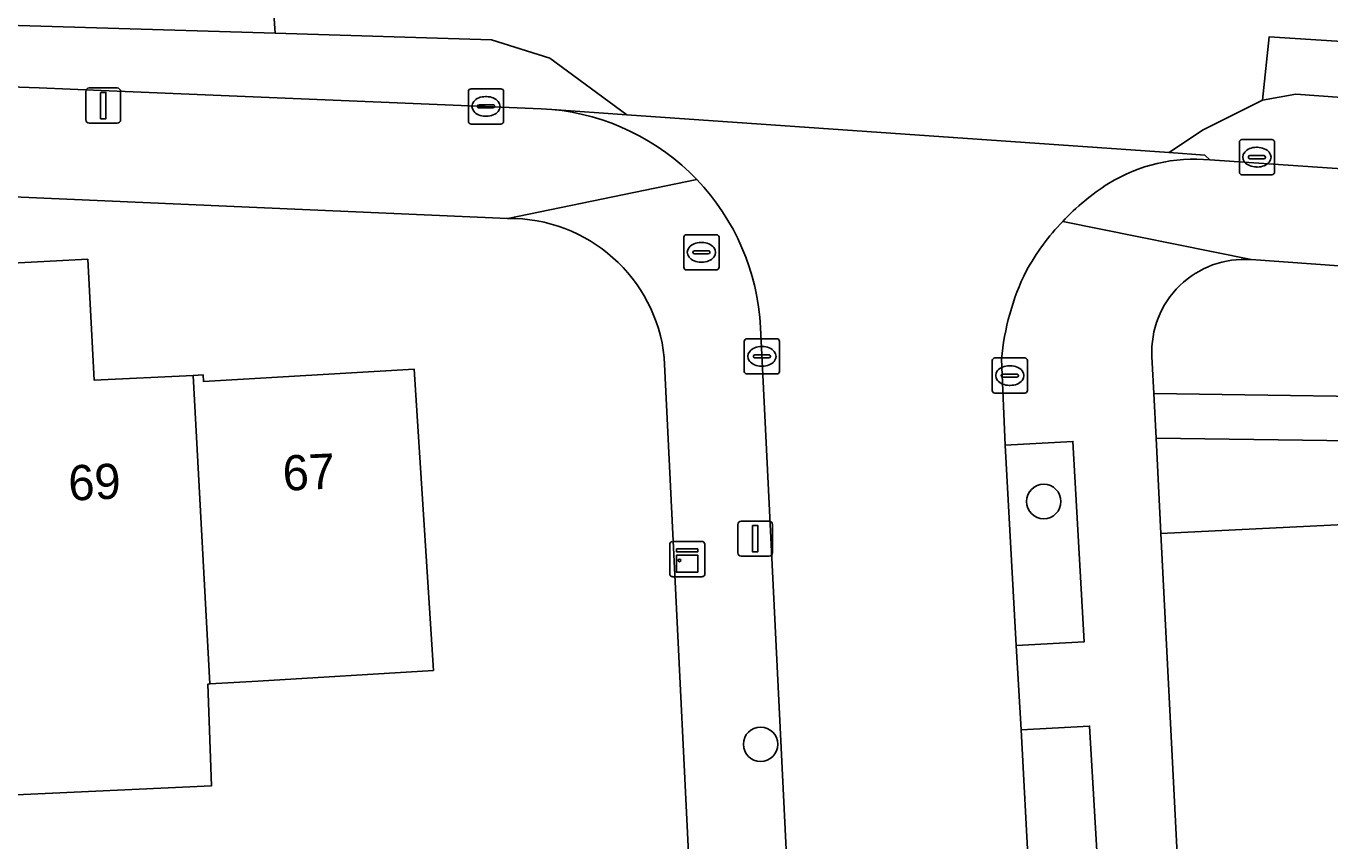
# Model space of a CAD drawing. Extents: x 161084 to 161928, y 385354 to 386522.
# Drawn here: x 161294.37 to 161331.43, y 386132.82 to 386155.98 of the extents above; entities that cross this region are included whole.
import ezdxf

# ---------------------------------------------------------------- set-up
doc = ezdxf.new("R2010")
doc.units = 0
for name, color, linetype in [('IMGEO_Boom', 7, 'Continuous'), ('IMGEO_Brandkraan', 7, 'Continuous'), ('IMGEO_Erf', 7, 'Continuous'), ('IMGEO_Groenvoorziening', 7, 'Continuous'), ('IMGEO_Hek', 7, 'Continuous'), ('IMGEO_Kast', 7, 'Continuous'), ('IMGEO_Kolk', 7, 'Continuous'), ('IMGEO_Lichtmast', 7, 'Continuous'), ('IMGEO_Pand', 7, 'Continuous'), ('IMGEO_Pand_nummerreeks', 7, 'Continuous'), ('IMGEO_Parkeervlak_gesloten', 7, 'Continuous'), ('IMGEO_Rijbaan_lokaal_gesloten', 7, 'Continuous'), ('IMGEO_Rijbaan_lokaal_open', 7, 'Continuous'), ('IMGEO_Voetpad_open', 7, 'Continuous')]:
    doc.layers.add(name, color=color, linetype=linetype)

msp = doc.modelspace()

# ---------------------------------------------------------------- linework, layer by layer
at = {"layer": 'IMGEO_Boom'}
for centre in [(161323.299, 386142.465), (161315.249, 386135.563)]:
    msp.add_circle(centre, 0.489, dxfattribs=at)
at = {"layer": 'IMGEO_Brandkraan'}
for p, q in [((161313.067, 386149.123), (161313.067, 386149.975)), ((161313.142, 386150.049), (161313.994, 386150.049)), ((161313.555, 386149.829), (161313.58, 386149.829)), ((161314.068, 386149.975), (161314.068, 386149.123)), ((161313.326, 386149.543), (161313.326, 386149.555)), ((161313.764, 386149.506), (161313.366, 386149.506)), ((161313.369, 386149.592), (161313.767, 386149.592)), ((161313.81, 386149.555), (161313.81, 386149.543)), ((161313.994, 386149.049), (161313.142, 386149.049)), ((161313.578, 386149.269), (161313.553, 386149.269))]:
    msp.add_line(p, q, dxfattribs=at)
for points in [[(161313.067, 386149.123), (161313.067, 386149.975)], [(161313.142, 386150.049), (161313.994, 386150.049)], [(161314.068, 386149.975), (161314.068, 386149.123)], [(161313.994, 386149.049), (161313.142, 386149.049)]]:
    msp.add_lwpolyline(points, dxfattribs=at)
for centre, radius, start, end in [((161313.144, 386149.973), 0.0765, 91.552, 178.448), ((161313.144, 386149.973), 0.0765, 91.552, 178.448), ((161313.992, 386149.973), 0.0765, 1.552, 88.448), ((161313.992, 386149.973), 0.0765, 1.552, 88.448), ((161313.366, 386149.552), 0.0403, 85.8775, 175.7526), ((161313.363, 386149.542), 0.0366, 178.938, 274.7102), ((161313.767, 386149.549), 0.043, 264.8664, 352.4533), ((161313.771, 386149.554), 0.0386, 1.7309, 96.639), ((161313.144, 386149.125), 0.0765, 181.552, 268.448), ((161313.144, 386149.125), 0.0765, 181.552, 268.448), ((161313.992, 386149.125), 0.0765, 271.552, 358.448), ((161313.992, 386149.125), 0.0765, 271.552, 358.448)]:
    msp.add_arc(centre, radius, start, end, dxfattribs=at)
for centre, major_axis, ratio, start_param, end_param in [((161313.554, 386149.549), (-0.387, 0.002), 0.722429, 4.712389, 7.853982), ((161313.579, 386149.549), (-0.39, 0.002), 0.717154, 1.570796, 4.712389)]:
    msp.add_ellipse(centre, major_axis=major_axis, ratio=ratio, start_param=start_param, end_param=end_param, dxfattribs=at)
at = {"layer": 'IMGEO_Erf'}
for points in [[(161308.06, 386150.51), (161293.144, 386151.165)], [(161292.892, 386149.179), (161296.121, 386149.354), (161296.307, 386145.913), (161299.12, 386146.051), (161299.406, 386146.065), (161299.417, 386145.876), (161305.406, 386146.224), (161305.951, 386137.661), (161300.961, 386137.353), (161299.596, 386137.278), (161299.538, 386137.273), (161299.638, 386134.377), (161293.683, 386134.108)], [(161293.068, 386124.722), (161295.221, 386124.913), (161295.092, 386127.372), (161300.05, 386127.633), (161300.18, 386125.161), (161301.546, 386125.23), (161301.425, 386127.712), (161306.376, 386127.954), (161306.19, 386131.777), (161309.467, 386131.936), (161309.774, 386125.631), (161313.524, 386125.898), (161312.512, 386146.555)], [(161360.195, 386143.207), (161326.629, 386141.553), (161328.624, 386102.307), (161328.778, 386099.301), (161331.2, 386051.66), (161334.752, 386051.846)]]:
    msp.add_lwpolyline(points, dxfattribs=at)
msp.add_arc((161308.121, 386146.096), 4.415, 5.9705, 90.796, dxfattribs=at)
at = {"layer": 'IMGEO_Groenvoorziening'}
msp.add_lwpolyline([(161326.373, 386146.591), (161326.427, 386145.537), (161335.501, 386145.4), (161335.504, 386144.14), (161326.491, 386144.261), (161326.629, 386141.553), (161360.195, 386143.207), (161360.035, 386147.116), (161329.193, 386149.342)], dxfattribs=at)
for points in [[(161324.127, 386144.171), (161322.2, 386144.068), (161322.511, 386138.373), (161324.449, 386138.477)], [(161324.604, 386136.078), (161322.66, 386135.974), (161323.107, 386127.582), (161325.094, 386127.695)]]:
    msp.add_lwpolyline(points, close=True, dxfattribs=at)
msp.add_arc((161329.002, 386146.717), 2.632, 85.8341, 182.7467, dxfattribs=at)
at = {"layer": 'IMGEO_Hek'}
msp.add_lwpolyline([(161326.629, 386141.553), (161360.195, 386143.207)], dxfattribs=at)
at = {"layer": 'IMGEO_Kast'}
for p, q in [((161312.666, 386140.403), (161312.666, 386141.244)), ((161312.666, 386141.244), (161312.666, 386140.403)), ((161312.741, 386141.328), (161313.582, 386141.328)), ((161313.582, 386141.328), (161312.741, 386141.328)), ((161313.666, 386141.253), (161313.666, 386140.412)), ((161313.666, 386140.412), (161313.666, 386141.253)), ((161313.591, 386140.328), (161312.75, 386140.328)), ((161312.75, 386140.328), (161313.591, 386140.328))]:
    msp.add_line(p, q, dxfattribs=at)
for points in [[(161312.861, 386141.118), (161313.461, 386141.118), (161313.461, 386141.033), (161312.861, 386141.033), (161312.861, 386141.118)], [(161312.861, 386140.943), (161313.461, 386140.943), (161313.461, 386140.454), (161312.861, 386140.454), (161312.861, 386140.943)]]:
    msp.add_lwpolyline(points, dxfattribs=at)
msp.add_circle((161312.945, 386140.792), 0.0377, dxfattribs=at)
for centre, start, end in [((161312.744, 386141.25), 92.4484, 184.2845), ((161312.744, 386141.25), 92.4484, 184.2845), ((161313.588, 386141.25), 2.4484, 94.2845), ((161313.588, 386141.25), 2.4484, 94.2845), ((161312.744, 386140.406), 182.4484, 274.2845), ((161312.744, 386140.406), 182.4484, 274.2845), ((161313.588, 386140.406), 272.4484, 4.2845), ((161313.588, 386140.406), 272.4484, 4.2845)]:
    msp.add_arc(centre, 0.0779, start, end, dxfattribs=at)
at = {"layer": 'IMGEO_Kolk'}
for p, q in [((161307.018, 386154.196), (161307.87, 386154.196)), ((161306.943, 386153.27), (161306.943, 386154.122)), ((161307.431, 386153.976), (161307.456, 386153.976)), ((161307.944, 386154.122), (161307.944, 386153.27)), ((161307.202, 386153.69), (161307.202, 386153.702)), ((161307.64, 386153.653), (161307.242, 386153.653)), ((161307.245, 386153.739), (161307.643, 386153.739)), ((161307.454, 386153.416), (161307.429, 386153.416)), ((161307.686, 386153.702), (161307.686, 386153.69)), ((161307.87, 386153.196), (161307.018, 386153.196)), ((161328.859, 386151.828), (161328.859, 386152.68)), ((161328.934, 386152.754), (161329.786, 386152.754)), ((161329.86, 386152.68), (161329.86, 386151.828)), ((161329.161, 386152.297), (161329.559, 386152.297)), ((161329.347, 386152.534), (161329.372, 386152.534)), ((161329.118, 386152.248), (161329.118, 386152.26)), ((161329.556, 386152.211), (161329.158, 386152.211)), ((161329.37, 386151.974), (161329.345, 386151.974)), ((161329.602, 386152.26), (161329.602, 386152.248)), ((161329.786, 386151.754), (161328.934, 386151.754)), ((161314.787, 386146.165), (161314.787, 386147.017)), ((161314.862, 386147.091), (161315.714, 386147.091)), ((161315.275, 386146.871), (161315.3, 386146.871)), ((161315.788, 386147.017), (161315.788, 386146.165)), ((161315.046, 386146.585), (161315.046, 386146.597)), ((161315.484, 386146.548), (161315.086, 386146.548)), ((161315.089, 386146.634), (161315.487, 386146.634)), ((161315.53, 386146.597), (161315.53, 386146.585)), ((161321.834, 386145.619), (161321.834, 386146.471)), ((161321.909, 386146.545), (161322.761, 386146.545)), ((161322.835, 386146.471), (161322.835, 386145.619)), ((161315.714, 386146.091), (161314.862, 386146.091)), ((161315.298, 386146.311), (161315.273, 386146.311)), ((161322.093, 386146.039), (161322.093, 386146.051)), ((161322.531, 386146.002), (161322.133, 386146.002)), ((161322.136, 386146.088), (161322.534, 386146.088)), ((161322.322, 386146.325), (161322.347, 386146.325)), ((161322.577, 386146.051), (161322.577, 386146.039)), ((161322.345, 386145.765), (161322.32, 386145.765)), ((161322.761, 386145.545), (161321.909, 386145.545))]:
    msp.add_line(p, q, dxfattribs=at)
for points in [[(161307.018, 386154.196), (161307.87, 386154.196)], [(161306.943, 386153.27), (161306.943, 386154.122)], [(161307.944, 386154.122), (161307.944, 386153.27)], [(161307.87, 386153.196), (161307.018, 386153.196)], [(161328.859, 386151.828), (161328.859, 386152.68)], [(161328.934, 386152.754), (161329.786, 386152.754)], [(161329.86, 386152.68), (161329.86, 386151.828)], [(161329.786, 386151.754), (161328.934, 386151.754)], [(161314.787, 386146.165), (161314.787, 386147.017)], [(161314.862, 386147.091), (161315.714, 386147.091)], [(161315.788, 386147.017), (161315.788, 386146.165)], [(161321.834, 386145.619), (161321.834, 386146.471)], [(161321.909, 386146.545), (161322.761, 386146.545)], [(161322.835, 386146.471), (161322.835, 386145.619)], [(161315.714, 386146.091), (161314.862, 386146.091)], [(161322.761, 386145.545), (161321.909, 386145.545)]]:
    msp.add_lwpolyline(points, dxfattribs=at)
for centre, radius, start, end in [((161307.02, 386154.12), 0.0765, 91.552, 178.448), ((161307.02, 386154.12), 0.0765, 91.552, 178.448), ((161307.868, 386154.12), 0.0765, 1.552, 88.448), ((161307.868, 386154.12), 0.0765, 1.552, 88.448), ((161307.242, 386153.699), 0.0403, 85.8775, 175.7526), ((161307.239, 386153.689), 0.0366, 178.938, 274.7102), ((161307.643, 386153.696), 0.043, 264.8664, 352.4533), ((161307.647, 386153.701), 0.0386, 1.7309, 96.639), ((161307.02, 386153.272), 0.0765, 181.552, 268.448), ((161307.02, 386153.272), 0.0765, 181.552, 268.448), ((161307.868, 386153.272), 0.0765, 271.552, 358.448), ((161307.868, 386153.272), 0.0765, 271.552, 358.448), ((161328.936, 386152.678), 0.0765, 91.552, 178.448), ((161328.936, 386152.678), 0.0765, 91.552, 178.448), ((161329.784, 386152.678), 0.0765, 1.552, 88.448), ((161329.784, 386152.678), 0.0765, 1.552, 88.448), ((161329.158, 386152.257), 0.0403, 85.8775, 175.7526), ((161329.563, 386152.259), 0.0386, 1.7309, 96.639), ((161329.155, 386152.247), 0.0366, 178.938, 274.7102), ((161329.559, 386152.254), 0.043, 264.8664, 352.4533), ((161328.936, 386151.83), 0.0765, 181.552, 268.448), ((161328.936, 386151.83), 0.0765, 181.552, 268.448), ((161329.784, 386151.83), 0.0765, 271.552, 358.448), ((161329.784, 386151.83), 0.0765, 271.552, 358.448), ((161314.864, 386147.015), 0.0765, 91.552, 178.448), ((161314.864, 386147.015), 0.0765, 91.552, 178.448), ((161315.712, 386147.015), 0.0765, 1.552, 88.448), ((161315.712, 386147.015), 0.0765, 1.552, 88.448), ((161315.086, 386146.594), 0.0403, 85.8775, 175.7526), ((161315.083, 386146.584), 0.0366, 178.938, 274.7102), ((161315.487, 386146.591), 0.043, 264.8664, 352.4533), ((161315.491, 386146.596), 0.0386, 1.7309, 96.639), ((161321.911, 386146.469), 0.0765, 91.552, 178.448), ((161321.911, 386146.469), 0.0765, 91.552, 178.448), ((161322.759, 386146.469), 0.0765, 1.552, 88.448), ((161322.759, 386146.469), 0.0765, 1.552, 88.448), ((161314.864, 386146.167), 0.0765, 181.552, 268.448), ((161314.864, 386146.167), 0.0765, 181.552, 268.448), ((161315.712, 386146.167), 0.0765, 271.552, 358.448), ((161315.712, 386146.167), 0.0765, 271.552, 358.448), ((161322.133, 386146.048), 0.0403, 85.8775, 175.7526), ((161322.13, 386146.038), 0.0366, 178.938, 274.7102), ((161322.534, 386146.045), 0.043, 264.8664, 352.4533), ((161322.538, 386146.05), 0.0386, 1.7309, 96.639), ((161321.911, 386145.621), 0.0765, 181.552, 268.448), ((161321.911, 386145.621), 0.0765, 181.552, 268.448), ((161322.759, 386145.621), 0.0765, 271.552, 358.448), ((161322.759, 386145.621), 0.0765, 271.552, 358.448)]:
    msp.add_arc(centre, radius, start, end, dxfattribs=at)
for centre, major_axis, ratio, start_param, end_param in [((161307.43, 386153.696), (-0.387, 0.002), 0.722429, 4.712389, 7.853982), ((161307.455, 386153.696), (-0.39, 0.002), 0.717154, 1.570796, 4.712389), ((161329.346, 386152.254), (-0.387, 0.002), 0.722429, 4.712389, 7.853982), ((161329.371, 386152.254), (-0.39, 0.002), 0.717154, 1.570796, 4.712389), ((161315.274, 386146.591), (-0.387, 0.002), 0.722429, 4.712389, 7.853982), ((161315.299, 386146.591), (-0.39, 0.002), 0.717154, 1.570796, 4.712389), ((161322.321, 386146.045), (-0.387, 0.002), 0.722429, 4.712389, 7.853982), ((161322.346, 386146.045), (-0.39, 0.002), 0.717154, 1.570796, 4.712389)]:
    msp.add_ellipse(centre, major_axis=major_axis, ratio=ratio, start_param=start_param, end_param=end_param, dxfattribs=at)
at = {"layer": 'IMGEO_Lichtmast'}
for p, q in [((161296.167, 386154.221), (161296.957, 386154.221)), ((161296.957, 386154.221), (161296.167, 386154.221)), ((161296.067, 386153.321), (161296.067, 386154.121)), ((161296.067, 386154.121), (161296.067, 386153.321)), ((161297.057, 386154.121), (161297.057, 386153.321)), ((161297.057, 386153.321), (161297.057, 386154.121)), ((161296.957, 386153.221), (161296.167, 386153.221)), ((161296.167, 386153.221), (161296.957, 386153.221)), ((161314.6, 386141.008), (161314.6, 386141.808)), ((161314.6, 386141.808), (161314.6, 386141.008)), ((161314.7, 386141.908), (161315.49, 386141.908)), ((161315.49, 386141.908), (161314.7, 386141.908)), ((161315.59, 386141.808), (161315.59, 386141.008)), ((161315.59, 386141.008), (161315.59, 386141.808)), ((161315.49, 386140.908), (161314.7, 386140.908)), ((161314.7, 386140.908), (161315.49, 386140.908))]:
    msp.add_line(p, q, dxfattribs=at)
for points in [[(161296.487, 386154.096), (161296.637, 386154.096), (161296.637, 386153.346), (161296.487, 386153.346), (161296.487, 386154.096)], [(161315.02, 386141.783), (161315.17, 386141.783), (161315.17, 386141.033), (161315.02, 386141.033), (161315.02, 386141.783)]]:
    msp.add_lwpolyline(points, dxfattribs=at)
for centre, start, end in [((161296.167, 386154.121), 90, 180), ((161296.167, 386154.121), 90, 180), ((161296.957, 386154.121), 0, 90), ((161296.957, 386154.121), 360, 90), ((161296.167, 386153.321), 180, 270), ((161296.167, 386153.321), 180, 270), ((161296.957, 386153.321), 270, 0), ((161296.957, 386153.321), 270, 0), ((161314.7, 386141.808), 90, 180), ((161314.7, 386141.808), 90, 180), ((161315.49, 386141.808), 0, 90), ((161315.49, 386141.808), 360, 90), ((161314.7, 386141.008), 180, 270), ((161314.7, 386141.008), 180, 270), ((161315.49, 386141.008), 270, 0), ((161315.49, 386141.008), 270, 0)]:
    msp.add_arc(centre, 0.1, start, end, dxfattribs=at)
at = {"layer": 'IMGEO_Pand'}
for points in [[(161299.12, 386146.051), (161296.307, 386145.913), (161296.121, 386149.354), (161292.892, 386149.179), (161293.555, 386136.947), (161293.683, 386134.108), (161299.638, 386134.377), (161299.538, 386137.273), (161299.596, 386137.278)], [(161299.596, 386137.278), (161300.961, 386137.353), (161305.951, 386137.661), (161305.406, 386146.224), (161299.417, 386145.876), (161299.406, 386146.065), (161299.12, 386146.051)]]:
    msp.add_lwpolyline(points, close=True, dxfattribs=at)
at = {"layer": 'IMGEO_Parkeervlak_gesloten'}
for points in [[(161301.452, 386155.778), (161251.651, 386157.273), (161242.539, 386157.25), (161241.421, 386156.999), (161241.379, 386156.989), (161240.243, 386156.469), (161238.642, 386155.383), (161240.762, 386155.407), (161241.132, 386155.411), (161257.555, 386155.217), (161263.534, 386155.082), (161266.513, 386155.012), (161270.292, 386154.93), (161276.926, 386154.781), (161283.363, 386154.619), (161289.664, 386154.4), (161294.741, 386154.223), (161296.505, 386154.15), (161309.014, 386153.631), (161309.313, 386153.61), (161311.447, 386153.461), (161309.261, 386155.072), (161307.604, 386155.593)], [(161373.616, 386151.096), (161333.734, 386153.806), (161330.468, 386154.043), (161329.521, 386153.877), (161327.808, 386153.025), (161326.862, 386152.384), (161327.875, 386152.313), (161328.025, 386152.175), (161348.894, 386150.753), (161371.482, 386149.183), (161377.98, 386148.853), (161386.015, 386148.306), (161386.388, 386148.285), (161387.149, 386148.242), (161385.775, 386148.699), (161383.287, 386149.19)]]:
    msp.add_lwpolyline(points, close=True, dxfattribs=at)
at = {"layer": 'IMGEO_Rijbaan_lokaal_gesloten'}
for points in [[(161241.421, 386156.999), (161242.539, 386157.25), (161251.651, 386157.273), (161301.452, 386155.778), (161301.332, 386157.581), (161298.302, 386157.723), (161267.912, 386158.764), (161250.491, 386159.048), (161241.521, 386158.906)], [(161329.521, 386153.877), (161330.468, 386154.043), (161333.734, 386153.806), (161373.616, 386151.096), (161383.287, 386149.19), (161383.343, 386150.824), (161372.882, 386152.906), (161329.71, 386155.676)]]:
    msp.add_lwpolyline(points, close=True, dxfattribs=at)
msp.add_lwpolyline([(161301.332, 386157.581), (161301.452, 386155.778), (161307.604, 386155.593), (161309.261, 386155.072), (161311.447, 386153.461), (161326.862, 386152.384), (161327.808, 386153.025), (161329.521, 386153.877), (161329.71, 386155.676), (161372.882, 386152.906), (161383.343, 386150.824), (161383.287, 386149.19), (161385.775, 386148.699), (161387.149, 386148.242), (161388.305, 386148.176), (161389.961, 386148.106), (161395.814, 386147.74), (161411.463, 386146.498), (161416.389, 386150.182)], dxfattribs=at)
at = {"layer": 'IMGEO_Rijbaan_lokaal_open'}
for points in [[(161328.025, 386152.175), (161327.875, 386152.313), (161326.862, 386152.384), (161311.447, 386153.461), (161309.313, 386153.61)], [(161315.248, 386147.415), (161316.313, 386125.821), (161316.6, 386120.02), (161323.457, 386120.025), (161323.334, 386122.432), (161323.223, 386124.587), (161323.107, 386127.582), (161322.66, 386135.974), (161322.511, 386138.373)], [(161322.511, 386138.373), (161322.2, 386144.068), (161322.098, 386146.508)]]:
    msp.add_lwpolyline(points, dxfattribs=at)
for centre, radius, start, end in [((161308.707, 386147.089), 6.549, 43.7783, 84.6923), ((161327.577, 386147.563), 4.634, 84.4503, 121.7562), ((161308.701, 386147.087), 6.555, 2.8715, 43.7525), ((161328.959, 386145.554), 7.071, 122.7137, 136.4102), ((161328.881, 386145.63), 6.962, 136.42, 150.886), ((161329.137, 386145.894), 7.065, 153.7665, 175.0134)]:
    msp.add_arc(centre, radius, start, end, dxfattribs=at)
at = {"layer": 'IMGEO_Voetpad_open'}
for points in [[(161309.313, 386153.61), (161309.014, 386153.631), (161296.505, 386154.15), (161294.741, 386154.223), (161289.664, 386154.4), (161283.363, 386154.619), (161276.926, 386154.781), (161270.292, 386154.93), (161266.513, 386155.012), (161263.534, 386155.082), (161257.555, 386155.217), (161241.132, 386155.411), (161240.762, 386155.407)], [(161234.892, 386152.567), (161240.881, 386152.064), (161248.467, 386152.087), (161263.752, 386152.026), (161266.109, 386151.963), (161282.342, 386151.617), (161293.144, 386151.165), (161308.06, 386150.51), (161313.436, 386151.62)], [(161440.379, 386144.594), (161423.113, 386145.82), (161418.5, 386146.029), (161411.463, 386146.498), (161395.814, 386147.74), (161389.961, 386148.106), (161388.305, 386148.176), (161387.149, 386148.242), (161386.388, 386148.285), (161386.015, 386148.306), (161385.956, 386147.144), (161377.899, 386147.725), (161377.98, 386148.853), (161371.482, 386149.183), (161348.894, 386150.753), (161328.025, 386152.175)], [(161313.436, 386151.62), (161308.06, 386150.51)], [(161323.838, 386150.429), (161329.193, 386149.342), (161360.035, 386147.116)], [(161329.193, 386149.342), (161323.838, 386150.429)], [(161320.272, 386048.078), (161320.3, 386048.876), (161320.201, 386050.813), (161319.946, 386055.681), (161319.68, 386060.686), (161319.318, 386067.515), (161317.522, 386101.325), (161316.746, 386117.07), (161316.614, 386119.719), (161316.6, 386120.02), (161316.313, 386125.821), (161315.248, 386147.415)], [(161312.512, 386146.555), (161313.524, 386125.898), (161309.774, 386125.631), (161301.546, 386125.23), (161300.18, 386125.161), (161295.221, 386124.913), (161293.068, 386124.722), (161288.15, 386124.431), (161283.132, 386124.134), (161281.027, 386124.139), (161276.096, 386123.801), (161276.198, 386122.457), (161276.243, 386121.64), (161313.636, 386123.679), (161313.837, 386119.861), (161314.902, 386094.903), (161317.411, 386044.073), (161321.23, 386044.898), (161322.406, 386044.972)], [(161322.098, 386146.508), (161322.2, 386144.068), (161324.127, 386144.171), (161324.449, 386138.477), (161322.511, 386138.373), (161322.66, 386135.974), (161324.604, 386136.078), (161325.094, 386127.695), (161323.107, 386127.582), (161323.223, 386124.587), (161325.192, 386124.693), (161325.321, 386122.481), (161323.334, 386122.432), (161323.457, 386120.025), (161323.528, 386119.169), (161323.621, 386117.24), (161324.022, 386108.291)], [(161328.778, 386099.301), (161328.624, 386102.307), (161326.629, 386141.553), (161326.491, 386144.261), (161326.427, 386145.537), (161326.373, 386146.591)]]:
    msp.add_lwpolyline(points, dxfattribs=at)
msp.add_lwpolyline([(161326.491, 386144.261), (161335.504, 386144.14), (161335.501, 386145.4), (161326.427, 386145.537)], close=True, dxfattribs=at)
for centre, radius, start, end in [((161308.707, 386147.089), 6.549, 43.7783, 84.6923), ((161327.577, 386147.563), 4.634, 84.4503, 121.7562), ((161308.701, 386147.087), 6.555, 2.8715, 43.7525), ((161328.959, 386145.554), 7.071, 122.7137, 136.4102), ((161308.121, 386146.096), 4.415, 5.9705, 90.796), ((161328.881, 386145.63), 6.962, 136.42, 150.886), ((161329.002, 386146.717), 2.632, 85.8341, 182.7467), ((161329.137, 386145.894), 7.065, 153.7665, 175.0134)]:
    msp.add_arc(centre, radius, start, end, dxfattribs=at)

# ---------------------------------------------------------------- texts
at = {"layer": 'IMGEO_Pand_nummerreeks'}
for s, rotation, p in [('67', 2.6549, (161301.686, 386142.768)), ('69', 2.6528, (161295.593, 386142.486))]:
    msp.add_text(s, height=1, rotation=rotation, dxfattribs=at).set_placement(p)

doc.saveas('drawing.dxf')
